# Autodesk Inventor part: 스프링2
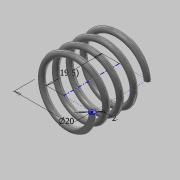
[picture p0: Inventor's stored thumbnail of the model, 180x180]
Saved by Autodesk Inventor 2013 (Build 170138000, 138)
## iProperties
Created: 2016-07
Part Number: 스프링2
Material: 스테인리스강
Document SubType Name: Modeling
Designer: dgall
Density: 8.08 g/cm^3
Mass: 6.23179 g
Surface Area: 15.7247 cm^2
Volume: 0.771261 cm^3
Author: dgall
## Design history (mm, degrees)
sketch "스케치1"
  geometry: L1 (0, 0)-(10, 0); L2 (10, 0)-(10, 19.5); L3 (10, 19.5)-(0, 19.5); L4 (0, 19.5)-(0, 0); C1 r 1 at (10, 0)
  constraints: 8 end point, 2 parallel, 1 centre point, 1 coincident, 1 horizontal, 1 perpendicular
  dimensions: "d0" = 20 diameter of L2 L4; "d2" = 19.5 distance of L3.end L1.start (derived); "d3" = 2 diameter of C1
feature "코일1" pitch "d4" = 10; turns "d6" = 4; dims "d5" = 19.5 (= d2), "d7" = 0, angle "d8" = 90 deg, angle "d9" = 90 deg, "d10" = 0, "d11" = 0
feature "분할1"
node "작업 평면1"
feature "분할2"
node "솔리드1"
